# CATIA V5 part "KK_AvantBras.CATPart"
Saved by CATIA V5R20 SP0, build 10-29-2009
Part number: av_bras
Bounding box of the stored display mesh (mm): x -89.97 to 509.97, y -50 to 50, z 0 to 50
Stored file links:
  G:\Khaled_CFAO_2011\ST2M\ST2M_GR2\tcorbin\Khaled\CAD_ThinkMOTION\KK_AvantBras.CATPart
  F:\Thinkmotionperso\assemblage robot\ass_skl_robot.CATProduct
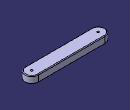
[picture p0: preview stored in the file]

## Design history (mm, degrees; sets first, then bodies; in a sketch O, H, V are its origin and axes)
External parameters (linked from other documents)
  `External.diametre perçage disque_arbre_avbras` = 15 mm
  `External.perçage avbrasbras` = 15 mm
  `External.longueur avbras` = 500 mm
  `External.largeur avbrasbras` = 100 mm
  `External.epaisseur avbrasbras` = 50 mm
Body1 (main body)
  Sketch1 on xy-plane, origin (0, 0, 0), H (1, 0, 0), V (0, 1, 0)
    line L1 (-40, 50) -> (460, 50)
    arc A1 centre (460, 0) radius 50 from (460, 50) to (460, -50) cw
    line L2 (460, -50) -> (-40, -50)
    arc A2 centre (-40, 0) radius 50 from (-40, -50) to (-40, 50) cw
    length L1 = 500 {= `External.longueur avbras`}
    distance L1 L2 = 100 {= `External.largeur avbrasbras`}
    horizontal: L1 H
    tangency: A1 L1, L2 A1, A2 L1, A2 L2
  Pad1: profile Sketch1, direction (0, 0, 1), length 50 {= `External.epaisseur avbrasbras`}
  Sketch2 on end face of Pad1, origin (203.1346, 8.6824, 50), H (1, 0, 0), V (0, 1, 0)
    point P1 (256.8654, -8.6824)
    reference projected line E1 (256.8654, 41.3176) -> (-243.1346, 41.3176) from edge [face of Pad1 from Sketch1.L1 | end face of Pad1]
    reference projected point E2 (256.8654, 41.3176) from vertex [face of Pad1 from Sketch1.L1 | end face of Pad1 | face of Pad1 from Sketch1.A1]
    distance P1 E1 = 50
    distance E2 P1 = 50
  Hole1: placed by Sketch2, at (460, 0, 50) direction (0, 0, -1), diameter 15 {= `External.perçage avbrasbras`}, through (limit type 3)
  Sketch3 on end face of Pad1, origin (198.3391, 12.0223, 50), H (1, 0, 0), V (0, 1, 0)
    point P1 (-238.3391, -12.0223)
    reference projected line E1 (261.6609, 37.9777) -> (-238.3391, 37.9777) from edge [face of Pad1 from Sketch1.L1 | end face of Pad1]
    reference projected point E2 (-238.3391, 37.9777) from vertex [face of Pad1 from Sketch1.L1 | end face of Pad1 | face of Pad1 from Sketch1.A2]
    distance P1 E1 = 50
    distance E2 P1 = 50
  Hole2: placed by Sketch3, at (-40, 0, 50) direction (0, 0, -1), diameter 15 {= `External.diametre perçage disque_arbre_avbras`}, through (limit type 3)
  Fillet1: radius 5, on edge [face of Pad1 from Sketch1.L1 | end face of Pad1]; edge [face of Pad1 from Sketch1.A2 | end face of Pad1]; edge [face of Pad1 from Sketch1.L2 | end face of Pad1]; edge [face of Pad1 from Sketch1.A1 | end face of Pad1]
